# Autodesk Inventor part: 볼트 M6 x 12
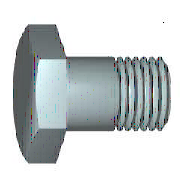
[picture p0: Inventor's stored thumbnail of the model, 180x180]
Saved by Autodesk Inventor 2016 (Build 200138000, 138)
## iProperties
IsCustomPart: 0
Created: 2012-02
Part Number: 볼트 M6 x 12
Material: 스테인리스강
Description: 6각 머리 나사. 제품 등급 C
Document SubType Name: Modeling
Standard: ISO 4018
Designer: mduedu
Standard Revision: Third edition 1999-08-15
Standards Organization: ISO
Language: ko-KR
Size Designation: M6 x 12
Categories: <MemberInstance><Categories><Category DisplayName="조임쇠" InternalName="e4da775c-781d-43d5-af7c-5136215cf5a6" Mnemonic="FSTN"><Category DisplayName="볼트" InternalN
Density: 8.08 g/cm^3
Appearance: 반광택
Author: mduedu
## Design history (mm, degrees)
node "WorkPlane1"
node "WorkPoint1"
node "MSC_A1"
node "MSC_PF1"
node "MSC_PT1"
body "Solid1"
node "스케치1"
sketch "스케치2"
  geometry: L1 (-5, 2.887)-(-5, -2.887); L2 (0, 5.773)-(-5, 2.887); L3 (5, 2.887)-(0, 5.773); L4 (5, -2.887)-(5, 2.887); L5 (0, -5.773)-(5, -2.887); L6 (-5, -2.887)-(0, -5.773); C1 r 5 at (0, 0); 1 further point
  constraints: 12 end point, 6 tangent, 2 parallel, 2 vertical, 1 centre point
  dimensions: "d1" = 10 diameter of C1 (= ParS); "d29" = 0 distance of point (0, 0) C1.centre; "d30" = 0 distance of C1.centre point (0, 0)
extrude "돌출1" new body sketch "스케치2" distance "d6" = 4 (= ParK); taper "d7" = 0 deg
revolve "회전1" stored, may be unused: angle "d14" = 360 deg
revolve "회전2" stored, may be unused: angle "d21" = 360 deg
chamfer "모따기1" distance "d22" = 0.5 (= 0.5 x PTC); stored, may be unused: second distance "d23" = 0.5 (= 0.5 x PTC), angle "d39" = 45 deg
fillet "모깎기1" dims "d24" = 0.25 (= r)
feature "스레드1" dims "d32" = 0, "b" = 10 (= NLG - 2 x PTC)
sketch "스케치3"
  geometry: L1 (5, 4)-(5.873, 4); L2 (5.873, 3.496)-(5, 4); L3 (5.873, 4)-(5.873, 3.496); L4 (0, -0.8)-(0, 4.8) reference; L5 (5.773, 0)-(5.773, 4) reference
  constraints: 6 end point, 1 horizontal, 1 vertical
  dimensions: "d25" = 0.1 distance between parallel lines of L5 L3; "d26" = 0 distance from line of L5.end L1; "d27" = 60 deg angle of L3 L2; "d28" = 5 distance from line of L4 L1.start (= 0.5 x ParS)
sketch "스케치4"
  geometry: L1 (0, -12)-(0, 0); L2 (-3, -12)-(0, -12); L3 (-3, 0)-(-3, -12); L4 (0, 0)-(-3, 0); L5 (0, -12)-(0, 0); L6 (-3.6, 0)-(0.6, 0) reference; L7 (0, -14.4)-(0, 2.4) reference
  constraints: 10 end point, 2 horizontal, 2 vertical
  dimensions: "d18" = 3 distance of L1.start L2.start (= 0.5 x NND); "d20" = 12 distance of L3.start L2.start (= NLG); "d33" = 0 distance between parallel lines of L7 L1; "d34" = 0 distance between parallel lines of L6 L4
other parameters: "NND" = 6 [user parameter; used in 2 equation terms], "NLG" = 12 [user parameter; used in 2 equation terms], "PTC" = 1 [user parameter; used in 3 equation terms], "ParK" = 4 [user parameter; used in 1 equation term], "ParS" = 10 [user parameter; used in 3 equation terms], "msp_es" = 5.77367 (= 0.577367 x ParS) [user parameter], "r" = 0.25 [user parameter; used in 1 equation term], "d2" = 15 (derived), "d4" = 17.32102 (derived), "d8" = 15 (derived), "d10" = 0 (derived), "d12" = 30 deg (derived), "d15" = 0 (derived), "d37" = 0, "d38" = 0, "d40" = 0, "d41" = 0, "d42" = 0, "THREADDIA" = 6 (= NND) [user parameter]
